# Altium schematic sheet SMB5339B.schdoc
size 127 x 101 mm
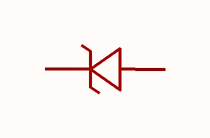
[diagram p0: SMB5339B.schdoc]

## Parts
D?  smb5339b  [SMB_L4.3-W3.6-LS5.4-RD]  (value not drawn)

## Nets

Not connected (* = marked no-connect by the designer): D? 1(K) 2(A)

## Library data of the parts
D? = smb5339b: 稳压值(标称值):5.6V;稳压值(范围):5.32V~5.88V;耗散功率(Pd):5W;; Manufacturer: CJ(江苏长电/长晶); AddInBom: yes; ModelId: 0be9a10c06a74ab7b6b40ad1b5d71adc; ModelTransform: 212.598,142.5194,0,0,0,0,0,0,0; Zener Voltage(Nom): 5.6V; Reverse Leakage Current (Ir): 1uA; Pd - Power Dissipation: 5W; Impedance(Zzt): 1Ω; Impedance(Zzk): 400Ω; Operating Junction Temperature Range: -55℃~+150℃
